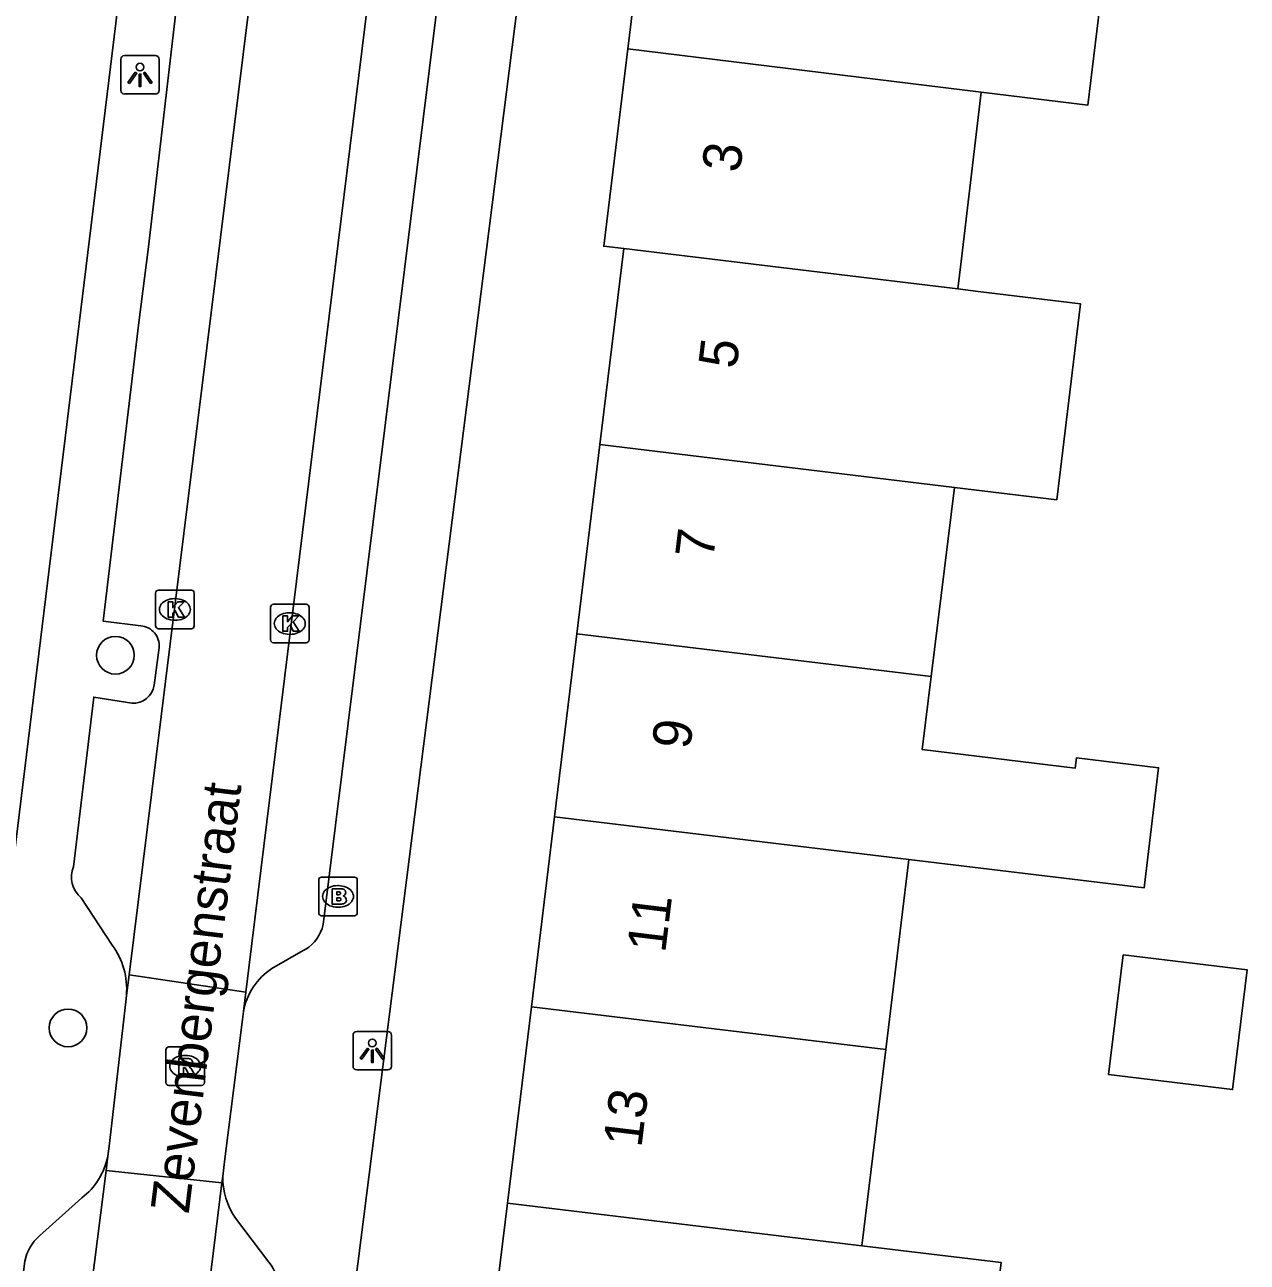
# Model space of a CAD drawing. Extents: x 158087 to 159494, y 382905 to 383981.
# Drawn here: x 158440.46 to 158472.19, y 383318.55 to 383350.68 of the extents above; entities that cross this region are included whole.
import ezdxf

# ---------------------------------------------------------------- set-up
doc = ezdxf.new("R2010")
doc.units = 0
for name, color, linetype in [('IMGEO_Boom', 7, 'Continuous'), ('IMGEO_Brandkraan', 7, 'Continuous'), ('IMGEO_Kolk', 7, 'Continuous'), ('IMGEO_Lichtpunt', 7, 'Continuous'), ('IMGEO_Openbare_ruimte_label', 7, 'Continuous'), ('IMGEO_Pand', 7, 'Continuous'), ('IMGEO_Pand_nummerreeks', 7, 'Continuous'), ('IMGEO_Rijbaan_lokaal_open', 7, 'Continuous'), ('IMGEO_Rioolput', 7, 'Continuous'), ('IMGEO_Voetpad_open', 7, 'Continuous')]:
    doc.layers.add(name, color=color, linetype=linetype)

msp = doc.modelspace()

# ---------------------------------------------------------------- linework, layer by layer
at = {"layer": 'IMGEO_Boom'}
for centre in [(158442.812, 383334.305), (158441.582, 383324.63)]:
    msp.add_circle(centre, 0.489, dxfattribs=at)
at = {"layer": 'IMGEO_Brandkraan'}
for p, q in [((158448.164, 383328.544), (158449.016, 383328.544)), ((158448.089, 383327.618), (158448.089, 383328.47)), ((158448.577, 383328.324), (158448.602, 383328.324)), ((158449.09, 383328.47), (158449.09, 383327.618)), ((158449.016, 383327.544), (158448.164, 383327.544)), ((158448.6, 383327.764), (158448.575, 383327.764))]:
    msp.add_line(p, q, dxfattribs=at)
for points in [[(158448.164, 383328.544), (158449.016, 383328.544)], [(158448.089, 383327.618), (158448.089, 383328.47)], [(158448.437, 383328.244), (158448.437, 383327.844), (158448.65, 383327.844)], [(158448.668, 383328.244), (158448.437, 383328.244)], [(158449.09, 383328.47), (158449.09, 383327.618)], [(158448.616, 383328.163), (158448.562, 383328.163), (158448.562, 383328.087)], [(158448.562, 383328.087), (158448.615, 383328.087)], [(158448.624, 383328.011), (158448.562, 383328.011), (158448.562, 383327.93)], [(158448.562, 383327.93), (158448.624, 383327.93)], [(158449.016, 383327.544), (158448.164, 383327.544)]]:
    msp.add_lwpolyline(points, dxfattribs=at)
for centre, radius, start, end in [((158448.166, 383328.468), 0.0765, 91.552, 178.448), ((158448.166, 383328.468), 0.0765, 91.552, 178.448), ((158449.014, 383328.468), 0.0765, 1.552, 88.448), ((158449.014, 383328.468), 0.0765, 1.552, 88.448), ((158448.672, 383328.099), 0.145, 59.4692, 91.5367), ((158448.697, 383328.146), 0.0922, 285.5137, 58.1501), ((158448.617, 383328.125), 0.0379, 267.8285, 90.9355), ((158448.625, 383327.97), 0.0404, 269.8759, 90.5077), ((158448.656, 383328.095), 0.251, 268.6676, 293.5347), ((158448.702, 383327.954), 0.105, 301.3115, 78.989), ((158448.166, 383327.62), 0.0765, 181.552, 268.448), ((158448.166, 383327.62), 0.0765, 181.552, 268.448), ((158449.014, 383327.62), 0.0765, 271.552, 358.448), ((158449.014, 383327.62), 0.0765, 271.552, 358.448)]:
    msp.add_arc(centre, radius, start, end, dxfattribs=at)
for centre, major_axis, ratio, start_param, end_param in [((158448.576, 383328.044), (-0.387, 0.002), 0.722429, 4.712389, 7.853982), ((158448.601, 383328.044), (-0.39, 0.002), 0.717154, 1.570796, 4.712389)]:
    msp.add_ellipse(centre, major_axis=major_axis, ratio=ratio, start_param=start_param, end_param=end_param, dxfattribs=at)
at = {"layer": 'IMGEO_Kolk'}
for p, q in [((158443.856, 383335.07), (158443.856, 383335.922)), ((158443.931, 383335.996), (158444.783, 383335.996)), ((158444.857, 383335.922), (158444.857, 383335.07)), ((158444.344, 383335.776), (158444.369, 383335.776)), ((158446.911, 383335.628), (158447.763, 383335.628)), ((158446.836, 383334.702), (158446.836, 383335.554)), ((158447.324, 383335.408), (158447.349, 383335.408)), ((158447.837, 383335.554), (158447.837, 383334.702)), ((158444.783, 383334.996), (158443.931, 383334.996)), ((158444.367, 383335.216), (158444.342, 383335.216)), ((158447.763, 383334.628), (158446.911, 383334.628)), ((158447.347, 383334.848), (158447.322, 383334.848))]:
    msp.add_line(p, q, dxfattribs=at)
for points in [[(158443.856, 383335.07), (158443.856, 383335.922)], [(158443.931, 383335.996), (158444.783, 383335.996)], [(158444.857, 383335.922), (158444.857, 383335.07)], [(158444.177, 383335.696), (158444.3, 383335.696), (158444.3, 383335.545), (158444.43, 383335.696), (158444.594, 383335.696), (158444.448, 383335.545), (158444.601, 383335.296), (158444.449, 383335.296), (158444.364, 383335.46), (158444.3, 383335.393), (158444.3, 383335.296), (158444.177, 383335.296), (158444.177, 383335.696)], [(158446.911, 383335.628), (158447.763, 383335.628)], [(158446.836, 383334.702), (158446.836, 383335.554)], [(158447.157, 383335.328), (158447.28, 383335.328), (158447.28, 383335.177), (158447.41, 383335.328), (158447.574, 383335.328), (158447.428, 383335.177), (158447.581, 383334.928), (158447.429, 383334.928), (158447.344, 383335.092), (158447.28, 383335.025), (158447.28, 383334.928), (158447.157, 383334.928), (158447.157, 383335.328)], [(158447.837, 383335.554), (158447.837, 383334.702)], [(158444.783, 383334.996), (158443.931, 383334.996)], [(158447.763, 383334.628), (158446.911, 383334.628)]]:
    msp.add_lwpolyline(points, dxfattribs=at)
for centre, start, end in [((158443.933, 383335.92), 91.552, 178.448), ((158443.933, 383335.92), 91.552, 178.448), ((158444.781, 383335.92), 1.552, 88.448), ((158444.781, 383335.92), 1.552, 88.448), ((158446.913, 383335.552), 91.552, 178.448), ((158446.913, 383335.552), 91.552, 178.448), ((158447.761, 383335.552), 1.552, 88.448), ((158447.761, 383335.552), 1.552, 88.448), ((158443.933, 383335.072), 181.552, 268.448), ((158443.933, 383335.072), 181.552, 268.448), ((158444.781, 383335.072), 271.552, 358.448), ((158444.781, 383335.072), 271.552, 358.448), ((158446.913, 383334.704), 181.552, 268.448), ((158446.913, 383334.704), 181.552, 268.448), ((158447.761, 383334.704), 271.552, 358.448), ((158447.761, 383334.704), 271.552, 358.448)]:
    msp.add_arc(centre, 0.0765, start, end, dxfattribs=at)
for centre, major_axis, ratio, start_param, end_param in [((158444.343, 383335.496), (-0.387, 0.002), 0.722429, 4.712389, 7.853982), ((158444.368, 383335.496), (-0.39, 0.002), 0.717154, 1.570796, 4.712389), ((158447.323, 383335.128), (-0.387, 0.002), 0.722429, 4.712389, 7.853982), ((158447.348, 383335.128), (-0.39, 0.002), 0.717154, 1.570796, 4.712389)]:
    msp.add_ellipse(centre, major_axis=major_axis, ratio=ratio, start_param=start_param, end_param=end_param, dxfattribs=at)
at = {"layer": 'IMGEO_Lichtpunt'}
for p, q in [((158442.951, 383349.78), (158442.951, 383348.973)), ((158442.951, 383349.78), (158442.951, 383348.973)), ((158443.853, 383349.875), (158443.045, 383349.875)), ((158443.853, 383349.875), (158443.045, 383349.875)), ((158443.947, 383348.973), (158443.947, 383349.78)), ((158443.947, 383348.973), (158443.947, 383349.78)), ((158443.045, 383348.879), (158443.853, 383348.879)), ((158443.045, 383348.879), (158443.853, 383348.879)), ((158448.98, 383324.44), (158448.98, 383323.633)), ((158448.98, 383324.44), (158448.98, 383323.633)), ((158449.882, 383324.535), (158449.074, 383324.535)), ((158449.882, 383324.535), (158449.074, 383324.535)), ((158449.976, 383323.633), (158449.976, 383324.44)), ((158449.976, 383323.633), (158449.976, 383324.44)), ((158449.074, 383323.539), (158449.882, 383323.539)), ((158449.074, 383323.539), (158449.882, 383323.539))]:
    msp.add_line(p, q, dxfattribs=at)
for points in [[(158443.325, 383349.444), (158443.364, 383349.416), (158443.176, 383349.154), (158443.138, 383349.181), (158443.325, 383349.444)], [(158443.427, 383349.396), (158443.474, 383349.396), (158443.474, 383349.074), (158443.427, 383349.074), (158443.427, 383349.396)], [(158443.537, 383349.416), (158443.575, 383349.443), (158443.762, 383349.181), (158443.723, 383349.153), (158443.537, 383349.416)], [(158449.354, 383324.104), (158449.393, 383324.076), (158449.205, 383323.814), (158449.167, 383323.841), (158449.354, 383324.104)], [(158449.456, 383324.056), (158449.503, 383324.056), (158449.503, 383323.734), (158449.456, 383323.734), (158449.456, 383324.056)], [(158449.566, 383324.076), (158449.604, 383324.103), (158449.791, 383323.841), (158449.752, 383323.813), (158449.566, 383324.076)]]:
    msp.add_lwpolyline(points, dxfattribs=at)
for centre in [(158443.45, 383349.578), (158449.479, 383324.238)]:
    msp.add_circle(centre, 0.0994, dxfattribs=at)
for centre, start, end in [((158443.045, 383349.78), 90, 180), ((158443.045, 383349.78), 90, 180), ((158443.853, 383349.78), 0, 90), ((158443.853, 383349.78), 0, 90), ((158443.045, 383348.973), 180, 270), ((158443.045, 383348.973), 180, 270), ((158443.853, 383348.973), 270, 0), ((158443.853, 383348.973), 270, 360), ((158449.074, 383324.44), 90, 180), ((158449.074, 383324.44), 90, 180), ((158449.882, 383324.44), 0, 90), ((158449.882, 383324.44), 0, 90), ((158449.074, 383323.633), 180, 270), ((158449.074, 383323.633), 180, 270), ((158449.882, 383323.633), 270, 0), ((158449.882, 383323.633), 270, 360)]:
    msp.add_arc(centre, 0.0946, start, end, dxfattribs=at)
at = {"layer": 'IMGEO_Pand'}
for points in [[(158456.734, 383355.164), (158456.111, 383350.053)], [(158465.284, 383348.929), (158468.055, 383348.59), (158468.677, 383353.717)], [(158456.111, 383350.053), (158455.486, 383344.927), (158456.008, 383344.864)], [(158465.284, 383348.929), (158456.111, 383350.053)], [(158464.676, 383343.817), (158464.76, 383344.526), (158465.022, 383346.727), (158465.284, 383348.929)], [(158456.008, 383344.864), (158455.388, 383339.774)], [(158464.676, 383343.817), (158456.008, 383344.864)], [(158464.586, 383338.665), (158467.245, 383338.344), (158467.858, 383343.433), (158465.206, 383343.753), (158464.676, 383343.817)], [(158454.789, 383334.86), (158455.388, 383339.774)], [(158455.388, 383339.774), (158464.586, 383338.665)], [(158463.986, 383333.75), (158464.586, 383338.665)], [(158454.789, 383334.86), (158454.21, 383330.112)], [(158463.986, 383333.75), (158454.789, 383334.86)], [(158463.408, 383329.002), (158469.511, 383328.264), (158469.888, 383331.386), (158467.757, 383331.643), (158467.725, 383331.376), (158463.755, 383331.855), (158463.986, 383333.75)], [(158453.609, 383325.179), (158454.21, 383330.112)], [(158454.21, 383330.112), (158463.408, 383329.002)], [(158462.806, 383324.069), (158463.408, 383329.002)], [(158468.964, 383326.529), (158468.585, 383323.42), (158471.809, 383323.027), (158472.188, 383326.136), (158468.964, 383326.529)], [(158453.609, 383325.179), (158452.987, 383320.083)], [(158462.806, 383324.069), (158453.609, 383325.179)], [(158462.185, 383318.973), (158462.806, 383324.069)], [(158452.987, 383320.083), (158452.412, 383315.364)], [(158452.987, 383320.083), (158462.185, 383318.973)], [(158461.61, 383314.254), (158461.903, 383316.656), (158465.523, 383316.22), (158465.802, 383318.537), (158462.185, 383318.973)]]:
    msp.add_lwpolyline(points, dxfattribs=at)
at = {"layer": 'IMGEO_Rijbaan_lokaal_open'}
for points in [[(158443.166, 383326.005), (158449.915, 383380.52)], [(158452.917, 383380.115), (158446.195, 383325.557)], [(158443.099, 383325.475), (158443.166, 383326.005)], [(158446.195, 383325.557), (158443.166, 383326.005)], [(158442.615, 383321.298), (158442.648, 383321.561), (158443.079, 383325.309), (158443.099, 383325.475)], [(158446.195, 383325.557), (158446.135, 383325.054)], [(158446.135, 383325.054), (158446.111, 383324.852), (158445.652, 383321.227), (158445.598, 383320.783)], [(158442.615, 383321.298), (158442.568, 383320.923)], [(158442.568, 383320.923), (158441.518, 383312.601), (158439.039, 383292.28), (158436.948, 383275.037), (158435.718, 383265.126)], [(158442.568, 383320.923), (158445.576, 383320.606)], [(158445.576, 383320.606), (158444.538, 383312.135), (158442.032, 383291.844), (158441.307, 383285.994)], [(158445.598, 383320.783), (158445.576, 383320.606)]]:
    msp.add_lwpolyline(points, dxfattribs=at)
at = {"layer": 'IMGEO_Rioolput'}
for p, q in [((158444.122, 383323.21), (158444.122, 383324.062)), ((158444.197, 383324.136), (158445.049, 383324.136)), ((158445.123, 383324.062), (158445.123, 383323.21)), ((158444.61, 383323.916), (158444.635, 383323.916)), ((158445.049, 383323.136), (158444.197, 383323.136)), ((158444.633, 383323.356), (158444.608, 383323.356))]:
    msp.add_line(p, q, dxfattribs=at)
for points in [[(158444.122, 383323.21), (158444.122, 383324.062)], [(158444.197, 383324.136), (158445.049, 383324.136)], [(158445.123, 383324.062), (158445.123, 383323.21)], [(158444.711, 383323.834), (158444.459, 383323.836), (158444.459, 383323.436)], [(158444.637, 383323.755), (158444.583, 383323.755), (158444.583, 383323.674)], [(158444.459, 383323.436), (158444.583, 383323.436), (158444.583, 383323.598), (158444.594, 383323.598)], [(158444.583, 383323.674), (158444.635, 383323.674)], [(158444.641, 383323.569), (158444.712, 383323.436), (158444.852, 383323.436), (158444.787, 383323.562)], [(158445.049, 383323.136), (158444.197, 383323.136)]]:
    msp.add_lwpolyline(points, dxfattribs=at)
for centre, radius, start, end in [((158444.199, 383324.06), 0.0765, 91.552, 178.448), ((158444.199, 383324.06), 0.0765, 91.552, 178.448), ((158445.047, 383324.06), 0.0765, 1.552, 88.448), ((158445.047, 383324.06), 0.0765, 1.552, 88.448), ((158444.643, 383323.659), 0.0964, 77.0061, 93.1865), ((158444.657, 383323.716), 0.0378, 276.6634, 79.6772), ((158444.71, 383323.724), 0.109, 350.3612, 89.416), ((158444.708, 383323.724), 0.112, 277.5842, 350.9817), ((158444.593, 383323.545), 0.0533, 26.0293, 88.6989), ((158444.619, 383323.863), 0.19, 274.7715, 282.9687), ((158444.692, 383323.509), 0.108, 29.5134, 73.7905), ((158444.199, 383323.212), 0.0765, 181.552, 268.448), ((158444.199, 383323.212), 0.0765, 181.552, 268.448), ((158445.047, 383323.212), 0.0765, 271.552, 358.448), ((158445.047, 383323.212), 0.0765, 271.552, 358.448)]:
    msp.add_arc(centre, radius, start, end, dxfattribs=at)
for centre, major_axis, ratio, start_param, end_param in [((158444.609, 383323.636), (-0.387, 0.002), 0.722429, 4.712389, 7.853982), ((158444.634, 383323.636), (-0.39, 0.002), 0.717154, 1.570796, 4.712389)]:
    msp.add_ellipse(centre, major_axis=major_axis, ratio=ratio, start_param=start_param, end_param=end_param, dxfattribs=at)
at = {"layer": 'IMGEO_Voetpad_open'}
for points in [[(158443.468, 383335.072), (158442.49, 383335.192), (158443.422, 383342.946), (158443.669, 383344.914), (158444.651, 383353.313), (158444.921, 383355.387), (158445.693, 383361.529), (158445.911, 383363.477), (158446.825, 383370.794), (158447.092, 383372.795), (158447.689, 383377.833)], [(158454.363, 383376.955), (158448.202, 383327.311)], [(158443.915, 383359.655), (158434.771, 383284.796)], [(158444.949, 383285.754), (158453.777, 383355.357), (158453.937, 383355.354), (158453.954, 383355.494)], [(158443.821, 383333.525), (158443.947, 383334.505)], [(158441.722, 383328.813), (158442.249, 383333.218), (158443.24, 383333.063)], [(158442.727, 383326.781), (158441.922, 383328.006)], [(158447.743, 383326.67), (158446.875, 383326.174)], [(158440.843, 383319.229), (158441.941, 383320.215)], [(158445.931, 383319.688), (158446.79, 383318.545)], [(158441.068, 383315.421), (158440.071, 383315.563), (158440.463, 383318.576)]]:
    msp.add_lwpolyline(points, dxfattribs=at)
for centre, radius, start, end in [((158443.427, 383334.551), 0.522, 354.9254, 85.4567), ((158443.279, 383333.61), 0.548, 265.8729, 351.1092), ((158442.388, 383328.55), 0.716, 158.4289, 229.4096), ((158447.225, 383327.526), 1.001, 301.1969, 347.5926), ((158441.167, 383325.631), 1.938, 355.3955, 36.4026), ((158447.811, 383324.751), 1.703, 123.3356, 169.7578), ((158440.827, 383321.659), 1.824, 307.6326, 348.5757), ((158447.517, 383320.768), 1.919, 179.5661, 214.264), ((158441.612, 383318.344), 1.173, 131.01, 168.5972), ((158446.065, 383317.914), 0.961, 353.4423, 41.0455)]:
    msp.add_arc(centre, radius, start, end, dxfattribs=at)

# ---------------------------------------------------------------- texts
at = {"layer": 'IMGEO_Openbare_ruimte_label'}
msp.add_text('Zevenbergenstraat', height=1, rotation=82.9957, dxfattribs=at).set_placement((158444.714, 383319.79))
at = {"layer": 'IMGEO_Pand_nummerreeks'}
for s, rotation, p in [('3', 83.0502, (158459.021, 383346.816)), ('5', 83.0502, (158458.93, 383341.724)), ('7', 83.0503, (158458.327, 383336.782)), ('9', 83.0502, (158457.725, 383331.841)), ('11', 83.0503, (158457.081, 383326.556)), ('13', 83.0503, (158456.464, 383321.502))]:
    msp.add_text(s, height=1, rotation=rotation, dxfattribs=at).set_placement(p)

doc.saveas('drawing.dxf')
